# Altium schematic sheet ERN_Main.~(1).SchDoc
size A; SheetNumber: 1; SheetTotal: 1
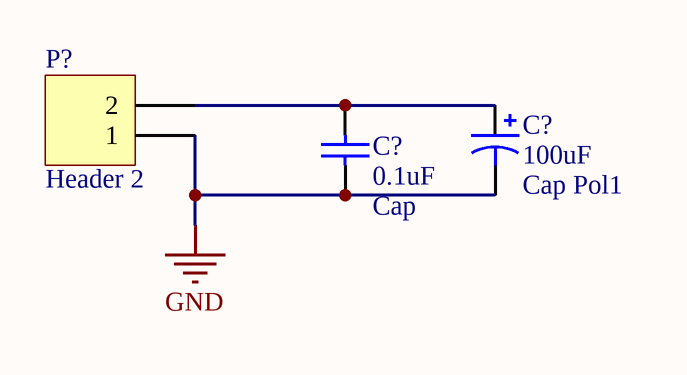
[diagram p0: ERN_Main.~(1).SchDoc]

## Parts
(Parts that share a designator on the sheet are numbered #1, #2 ... from top to bottom, then left to right.)
C?#1  Cap Pol1  value 100uF  [RB7.6-15]
C?#2  Cap  value 0.1uF  [RAD-0.3]
P?  Header 2  [HDR1X2]

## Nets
GND: C?#1.2 C?#2.1 P?.1
NetC?#1_1: C?#1.1 C?#2.2 P?.2

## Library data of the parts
C?#1 = Cap Pol1: Polarized Capacitor (Radial)
C?#2 = Cap: Capacitor
P? = Header 2: Header, 2-Pin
